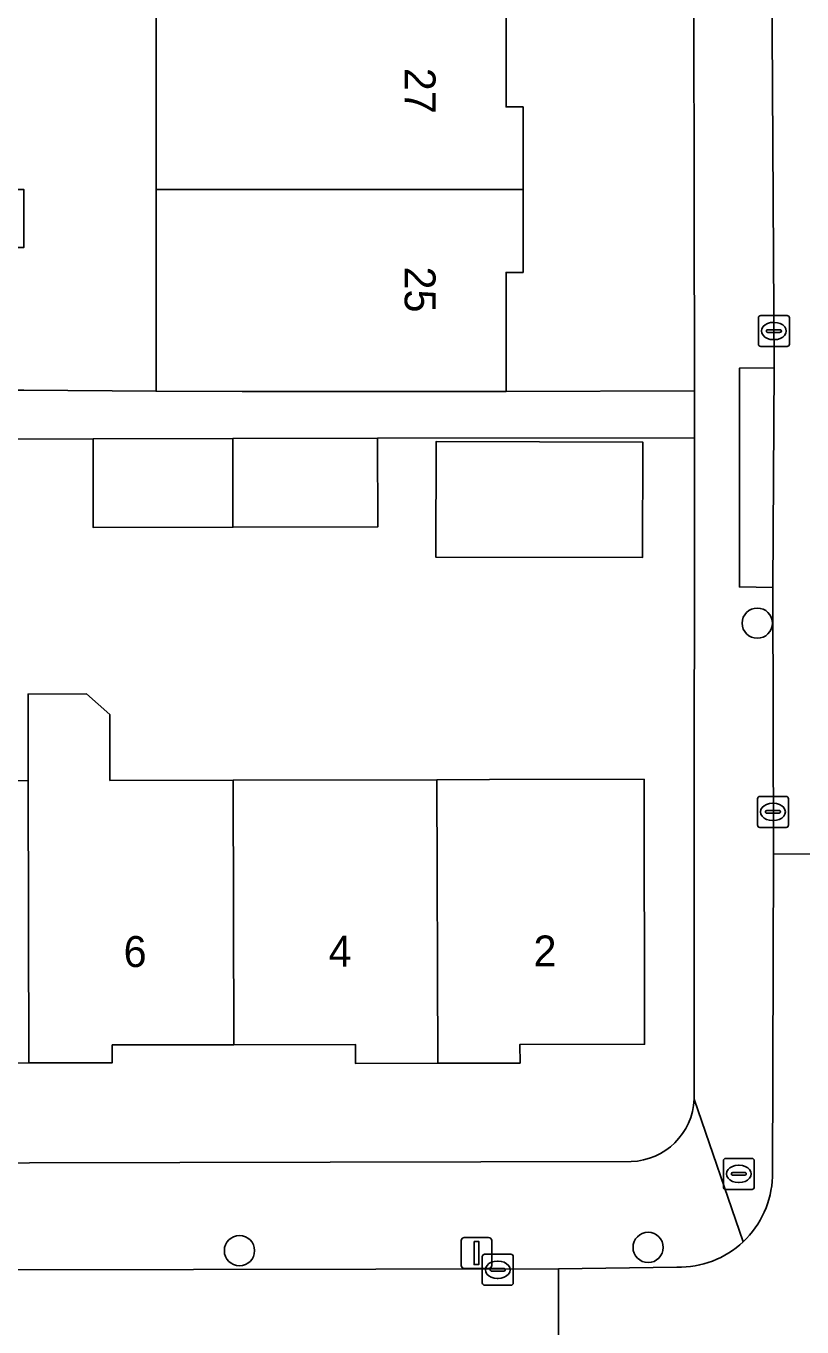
# Model space of a CAD drawing. Extents: x 160732 to 162107, y 387428 to 388479.
# Drawn here: x 161132.45 to 161157.55, y 387952.86 to 387994.94 of the extents above; entities that cross this region are included whole.
import ezdxf

# ---------------------------------------------------------------- set-up
doc = ezdxf.new("R2010")
doc.units = 0
for name, color, linetype in [('IMGEO_Boom', 7, 'Continuous'), ('IMGEO_Brandkraan', 7, 'Continuous'), ('IMGEO_Erf', 7, 'Continuous'), ('IMGEO_Kolk', 7, 'Continuous'), ('IMGEO_Lichtmast', 7, 'Continuous'), ('IMGEO_Muur', 7, 'Continuous'), ('IMGEO_Pand', 7, 'Continuous'), ('IMGEO_Pand_nummerreeks', 7, 'Continuous'), ('IMGEO_Rijbaan_lokaal_open', 7, 'Continuous'), ('IMGEO_Voetpad_open', 7, 'Continuous')]:
    doc.layers.add(name, color=color, linetype=linetype)

msp = doc.modelspace()

# ---------------------------------------------------------------- linework, layer by layer
at = {"layer": 'IMGEO_Boom'}
for centre in [(161156.103, 387975.628), (161152.574, 387955.438), (161139.358, 387955.333)]:
    msp.add_circle(centre, 0.489, dxfattribs=at)
at = {"layer": 'IMGEO_Brandkraan'}
for p, q in [((161155.007, 387957.39), (161155.007, 387958.242)), ((161155.082, 387958.316), (161155.934, 387958.316)), ((161155.495, 387958.096), (161155.52, 387958.096)), ((161156.008, 387958.242), (161156.008, 387957.39)), ((161155.266, 387957.81), (161155.266, 387957.822)), ((161155.704, 387957.773), (161155.306, 387957.773)), ((161155.309, 387957.859), (161155.707, 387957.859)), ((161155.75, 387957.822), (161155.75, 387957.81)), ((161155.934, 387957.316), (161155.082, 387957.316)), ((161155.518, 387957.536), (161155.493, 387957.536))]:
    msp.add_line(p, q, dxfattribs=at)
for points in [[(161155.007, 387957.39), (161155.007, 387958.242)], [(161155.082, 387958.316), (161155.934, 387958.316)], [(161156.008, 387958.242), (161156.008, 387957.39)], [(161155.934, 387957.316), (161155.082, 387957.316)]]:
    msp.add_lwpolyline(points, dxfattribs=at)
for centre, radius, start, end in [((161155.084, 387958.24), 0.0765, 91.552, 178.448), ((161155.084, 387958.24), 0.0765, 91.552, 178.448), ((161155.932, 387958.24), 0.0765, 1.552, 88.448), ((161155.932, 387958.24), 0.0765, 1.552, 88.448), ((161155.306, 387957.819), 0.0403, 85.8775, 175.7526), ((161155.303, 387957.809), 0.0366, 178.938, 274.7102), ((161155.707, 387957.816), 0.043, 264.8664, 352.4533), ((161155.711, 387957.821), 0.0386, 1.7309, 96.639), ((161155.084, 387957.392), 0.0765, 181.552, 268.448), ((161155.084, 387957.392), 0.0765, 181.552, 268.448), ((161155.932, 387957.392), 0.0765, 271.552, 358.448), ((161155.932, 387957.392), 0.0765, 271.552, 358.448)]:
    msp.add_arc(centre, radius, start, end, dxfattribs=at)
for centre, major_axis, ratio, start_param, end_param in [((161155.494, 387957.816), (-0.387, 0.002), 0.722429, 4.712389, 7.853982), ((161155.519, 387957.816), (-0.39, 0.002), 0.717154, 1.570796, 4.712389)]:
    msp.add_ellipse(centre, major_axis=major_axis, ratio=ratio, start_param=start_param, end_param=end_param, dxfattribs=at)
at = {"layer": 'IMGEO_Erf'}
for points in [[(161147.98, 387996.03), (161147.981, 387992.327), (161148.53, 387992.328), (161148.53, 387989.652), (161148.531, 387986.973), (161147.978, 387986.973), (161147.979, 387983.124), (161154.07, 387983.142), (161153.967, 388045.181)], [(161129.495, 387996.124), (161129.503, 387993.682), (161129.313, 387993.681), (161129.313, 387991.792), (161129.313, 387989.652), (161132.386, 387989.652), (161132.386, 387987.784), (161129.313, 387987.784), (161127.893, 387987.784), (161127.903, 387984.571), (161127.914, 387983.109), (161129.313, 387983.166), (161132.386, 387983.166), (161136.66, 387983.129), (161136.66, 387989.652), (161136.66, 387996.03)], [(161154.078, 387978.287), (161154.072, 387981.627), (161143.824, 387981.61), (161143.831, 387978.74), (161139.144, 387978.73), (161134.63, 387978.72), (161134.624, 387981.59), (161130.583, 387981.582)], [(161154.063, 387960.237), (161154.064, 387969.974), (161154.078, 387978.287)], [(161125.918, 387970.523), (161132.528, 387970.537), (161132.523, 387973.336), (161134.415, 387973.34), (161135.161, 387972.672), (161135.166, 387970.543), (161139.159, 387970.551), (161145.744, 387970.565), (161147.444, 387970.569), (161152.443, 387970.58), (161152.462, 387962.009), (161148.43, 387962.001), (161148.432, 387961.398), (161145.77, 387961.392), (161143.11, 387961.387), (161143.109, 387962.002), (161139.175, 387961.993), (161135.242, 387961.985), (161135.243, 387961.41), (161132.545, 387961.405), (161129.846, 387961.399)], [(161091.407, 387957.982), (161108.242, 387957.975), (161108.23, 387958.121), (161152.025, 387958.213)]]:
    msp.add_lwpolyline(points, dxfattribs=at)
msp.add_lwpolyline([(161145.714, 387981.5), (161152.401, 387981.486), (161152.393, 387977.753), (161145.707, 387977.767)], close=True, dxfattribs=at)
msp.add_arc((161151.949, 387960.327), 2.116, 272.0485, 357.5566, dxfattribs=at)
at = {"layer": 'IMGEO_Kolk'}
for p, q in [((161156.141, 387984.652), (161156.141, 387985.504)), ((161156.216, 387985.578), (161157.068, 387985.578)), ((161156.629, 387985.358), (161156.654, 387985.358)), ((161157.142, 387985.504), (161157.142, 387984.652)), ((161156.4, 387985.072), (161156.4, 387985.084)), ((161156.838, 387985.035), (161156.44, 387985.035)), ((161156.443, 387985.121), (161156.841, 387985.121)), ((161156.884, 387985.084), (161156.884, 387985.072)), ((161157.068, 387984.578), (161156.216, 387984.578)), ((161156.652, 387984.798), (161156.627, 387984.798)), ((161156.111, 387969.097), (161156.111, 387969.949)), ((161156.186, 387970.023), (161157.038, 387970.023)), ((161156.599, 387969.803), (161156.624, 387969.803)), ((161157.112, 387969.949), (161157.112, 387969.097)), ((161156.37, 387969.517), (161156.37, 387969.529)), ((161156.808, 387969.48), (161156.41, 387969.48)), ((161156.413, 387969.566), (161156.811, 387969.566)), ((161156.854, 387969.529), (161156.854, 387969.517)), ((161157.038, 387969.023), (161156.186, 387969.023)), ((161156.622, 387969.243), (161156.597, 387969.243)), ((161147.211, 387954.289), (161147.211, 387955.141)), ((161147.286, 387955.215), (161148.138, 387955.215)), ((161148.212, 387955.141), (161148.212, 387954.289)), ((161147.47, 387954.709), (161147.47, 387954.721)), ((161147.908, 387954.672), (161147.51, 387954.672)), ((161147.513, 387954.758), (161147.911, 387954.758)), ((161147.699, 387954.995), (161147.724, 387954.995)), ((161147.954, 387954.721), (161147.954, 387954.709)), ((161148.138, 387954.215), (161147.286, 387954.215)), ((161147.722, 387954.435), (161147.697, 387954.435))]:
    msp.add_line(p, q, dxfattribs=at)
for points in [[(161156.141, 387984.652), (161156.141, 387985.504)], [(161156.216, 387985.578), (161157.068, 387985.578)], [(161157.142, 387985.504), (161157.142, 387984.652)], [(161157.068, 387984.578), (161156.216, 387984.578)], [(161156.111, 387969.097), (161156.111, 387969.949)], [(161156.186, 387970.023), (161157.038, 387970.023)], [(161157.112, 387969.949), (161157.112, 387969.097)], [(161157.038, 387969.023), (161156.186, 387969.023)], [(161147.211, 387954.289), (161147.211, 387955.141)], [(161147.286, 387955.215), (161148.138, 387955.215)], [(161148.212, 387955.141), (161148.212, 387954.289)], [(161148.138, 387954.215), (161147.286, 387954.215)]]:
    msp.add_lwpolyline(points, dxfattribs=at)
for centre, radius, start, end in [((161156.218, 387985.502), 0.0765, 91.552, 178.448), ((161156.218, 387985.502), 0.0765, 91.552, 178.448), ((161157.066, 387985.502), 0.0765, 1.552, 88.448), ((161157.066, 387985.502), 0.0765, 1.552, 88.448), ((161156.44, 387985.081), 0.0403, 85.8775, 175.7526), ((161156.437, 387985.071), 0.0366, 178.938, 274.7102), ((161156.841, 387985.078), 0.043, 264.8664, 352.4533), ((161156.845, 387985.083), 0.0386, 1.7309, 96.639), ((161156.218, 387984.654), 0.0765, 181.552, 268.448), ((161156.218, 387984.654), 0.0765, 181.552, 268.448), ((161157.066, 387984.654), 0.0765, 271.552, 358.448), ((161157.066, 387984.654), 0.0765, 271.552, 358.448), ((161156.188, 387969.947), 0.0765, 91.552, 178.448), ((161156.188, 387969.947), 0.0765, 91.552, 178.448), ((161157.036, 387969.947), 0.0765, 1.552, 88.448), ((161157.036, 387969.947), 0.0765, 1.552, 88.448), ((161156.41, 387969.526), 0.0403, 85.8775, 175.7526), ((161156.407, 387969.516), 0.0366, 178.938, 274.7102), ((161156.811, 387969.523), 0.043, 264.8664, 352.4533), ((161156.815, 387969.528), 0.0386, 1.7309, 96.639), ((161156.188, 387969.099), 0.0765, 181.552, 268.448), ((161156.188, 387969.099), 0.0765, 181.552, 268.448), ((161157.036, 387969.099), 0.0765, 271.552, 358.448), ((161157.036, 387969.099), 0.0765, 271.552, 358.448), ((161147.288, 387955.139), 0.0765, 91.552, 178.448), ((161147.288, 387955.139), 0.0765, 91.552, 178.448), ((161148.136, 387955.139), 0.0765, 1.552, 88.448), ((161148.136, 387955.139), 0.0765, 1.552, 88.448), ((161147.51, 387954.718), 0.0403, 85.8775, 175.7526), ((161147.507, 387954.708), 0.0366, 178.938, 274.7102), ((161147.911, 387954.715), 0.043, 264.8664, 352.4533), ((161147.915, 387954.72), 0.0386, 1.7309, 96.639), ((161147.288, 387954.291), 0.0765, 181.552, 268.448), ((161147.288, 387954.291), 0.0765, 181.552, 268.448), ((161148.136, 387954.291), 0.0765, 271.552, 358.448), ((161148.136, 387954.291), 0.0765, 271.552, 358.448)]:
    msp.add_arc(centre, radius, start, end, dxfattribs=at)
for centre, major_axis, ratio, start_param, end_param in [((161156.628, 387985.078), (-0.387, 0.002), 0.722429, 4.712389, 7.853982), ((161156.653, 387985.078), (-0.39, 0.002), 0.717154, 1.570796, 4.712389), ((161156.598, 387969.523), (-0.387, 0.002), 0.722429, 4.712389, 7.853982), ((161156.623, 387969.523), (-0.39, 0.002), 0.717154, 1.570796, 4.712389), ((161147.698, 387954.715), (-0.387, 0.002), 0.722429, 4.712389, 7.853982), ((161147.723, 387954.715), (-0.39, 0.002), 0.717154, 1.570796, 4.712389)]:
    msp.add_ellipse(centre, major_axis=major_axis, ratio=ratio, start_param=start_param, end_param=end_param, dxfattribs=at)
at = {"layer": 'IMGEO_Lichtmast'}
for p, q in [((161146.526, 387954.858), (161146.526, 387955.658)), ((161146.526, 387955.658), (161146.526, 387954.858)), ((161146.626, 387955.758), (161147.416, 387955.758)), ((161147.416, 387955.758), (161146.626, 387955.758)), ((161147.516, 387955.658), (161147.516, 387954.858)), ((161147.516, 387954.858), (161147.516, 387955.658)), ((161147.416, 387954.758), (161146.626, 387954.758)), ((161146.626, 387954.758), (161147.416, 387954.758))]:
    msp.add_line(p, q, dxfattribs=at)
msp.add_lwpolyline([(161146.946, 387955.633), (161147.096, 387955.633), (161147.096, 387954.883), (161146.946, 387954.883), (161146.946, 387955.633)], dxfattribs=at)
for centre, start, end in [((161146.626, 387955.658), 90, 180), ((161146.626, 387955.658), 90, 180), ((161147.416, 387955.658), 0, 90), ((161147.416, 387955.658), 360, 90), ((161146.626, 387954.858), 180, 270), ((161146.626, 387954.858), 180, 270), ((161147.416, 387954.858), 270, 0), ((161147.416, 387954.858), 270, 0)]:
    msp.add_arc(centre, 0.1, start, end, dxfattribs=at)
at = {"layer": 'IMGEO_Muur'}
msp.add_lwpolyline([(161154.064, 387969.974), (161154.078, 387978.287)], dxfattribs=at)
at = {"layer": 'IMGEO_Pand'}
for points in [[(161136.66, 387989.652), (161148.53, 387989.652), (161148.53, 387992.328), (161147.981, 387992.327), (161147.98, 387996.03), (161139.444, 387996.03), (161136.66, 387996.03)], [(161142.98, 387983.123), (161147.979, 387983.124), (161147.978, 387986.973), (161148.531, 387986.973), (161148.53, 387989.652), (161136.66, 387989.652), (161136.66, 387983.129), (161139.448, 387983.122)], [(161134.624, 387981.59), (161134.63, 387978.72), (161139.144, 387978.73), (161139.138, 387981.6)], [(161143.831, 387978.74), (161143.824, 387981.61), (161139.138, 387981.6), (161139.144, 387978.73)], [(161152.401, 387981.486), (161145.714, 387981.5), (161145.707, 387977.767), (161152.393, 387977.753)], [(161135.166, 387970.543), (161135.161, 387972.672), (161134.415, 387973.34), (161132.523, 387973.336), (161132.528, 387970.537), (161132.545, 387961.405), (161135.243, 387961.41), (161135.242, 387961.985), (161139.175, 387961.993), (161139.159, 387970.551)], [(161125.94, 387961.99), (161129.844, 387961.998), (161129.846, 387961.399), (161132.545, 387961.405), (161132.528, 387970.537), (161125.918, 387970.523)], [(161145.744, 387970.565), (161139.159, 387970.551), (161139.175, 387961.993), (161143.109, 387962.002), (161143.11, 387961.387), (161145.77, 387961.392)], [(161145.77, 387961.392), (161148.432, 387961.398), (161148.43, 387962.001), (161152.462, 387962.009), (161152.443, 387970.58), (161147.444, 387970.569), (161145.744, 387970.565)]]:
    msp.add_lwpolyline(points, close=True, dxfattribs=at)
at = {"layer": 'IMGEO_Rijbaan_lokaal_open'}
msp.add_lwpolyline([(161156.469, 388045.652), (161156.521, 388005.647), (161156.651, 387983.882), (161156.61, 387976.781), (161156.629, 387968.165), (161161.565, 387968.157), (161161.475, 388044.985), (161161.475, 388045.161), (161161.493, 388045.766)], close=True, dxfattribs=at)
for points in [[(161161.581, 387967.173), (161161.565, 387968.157), (161156.629, 387968.165), (161156.595, 387957.722)], [(161149.664, 387949.751), (161149.674, 387954.744), (161114.238, 387954.68), (161107.154, 387954.663), (161086.596, 387954.673), (161034.34, 387954.542)], [(161153.502, 387954.799), (161149.674, 387954.744), (161149.664, 387949.751), (161150.715, 387949.719)]]:
    msp.add_lwpolyline(points, dxfattribs=at)
for centre, start, end in [((161153.579, 387957.817), 313.3662, 358.2033), ((161153.578, 387957.815), 268.5594, 313.3976)]:
    msp.add_arc(centre, 3.017, start, end, dxfattribs=at)
at = {"layer": 'IMGEO_Voetpad_open'}
for points in [[(161156.595, 387957.722), (161156.629, 387968.165), (161156.61, 387976.781), (161155.524, 387976.799), (161155.53, 387983.877), (161156.651, 387983.882), (161156.521, 388005.647), (161156.469, 388045.652)], [(161153.967, 388045.181), (161154.07, 387983.142), (161154.072, 387981.627), (161154.078, 387978.287), (161154.064, 387969.974), (161154.063, 387960.237), (161155.651, 387955.623)], [(161130.583, 387981.582), (161134.624, 387981.59), (161139.138, 387981.6), (161143.824, 387981.61), (161154.072, 387981.627), (161154.07, 387983.142), (161147.979, 387983.124), (161142.98, 387983.123), (161139.448, 387983.122), (161136.66, 387983.129), (161132.386, 387983.166)], [(161155.651, 387955.623), (161154.063, 387960.237)], [(161152.025, 387958.213), (161108.23, 387958.121), (161108.242, 387957.975), (161091.407, 387957.982)], [(161086.596, 387954.673), (161107.154, 387954.663), (161107.157, 387955.774), (161114.234, 387955.783), (161114.238, 387954.68), (161149.674, 387954.744), (161153.502, 387954.799)]]:
    msp.add_lwpolyline(points, dxfattribs=at)
msp.add_lwpolyline([(161156.61, 387976.781), (161156.651, 387983.882), (161155.53, 387983.877), (161155.524, 387976.799)], close=True, dxfattribs=at)
for centre, radius, start, end in [((161151.949, 387960.327), 2.116, 272.0485, 357.5566), ((161153.579, 387957.817), 3.017, 313.3662, 358.2033), ((161153.578, 387957.815), 3.017, 268.5594, 313.3976)]:
    msp.add_arc(centre, radius, start, end, dxfattribs=at)

# ---------------------------------------------------------------- texts
at = {"layer": 'IMGEO_Pand_nummerreeks'}
for s, rotation, p in [('27', 270.0021, (161144.699, 387993.592)), ('25', 270.0021, (161144.699, 387987.164)), ('6', 0.0735, (161135.611, 387964.508)), ('4', 0.0735, (161142.24, 387964.516)), ('2', 0.0735, (161148.868, 387964.525))]:
    msp.add_text(s, height=1, rotation=rotation, dxfattribs=at).set_placement(p)

doc.saveas('drawing.dxf')
